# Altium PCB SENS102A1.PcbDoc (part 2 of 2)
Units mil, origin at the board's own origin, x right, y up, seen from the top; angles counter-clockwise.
Board outline 2760 x 2518.85 mil, 4 copper layers (Top Layer, Signal Layer 1, Signal Layer 2, Bottom Layer), stack 62.2 mil thick; 53 components, 21 nets, 101 pads, 383 vias.
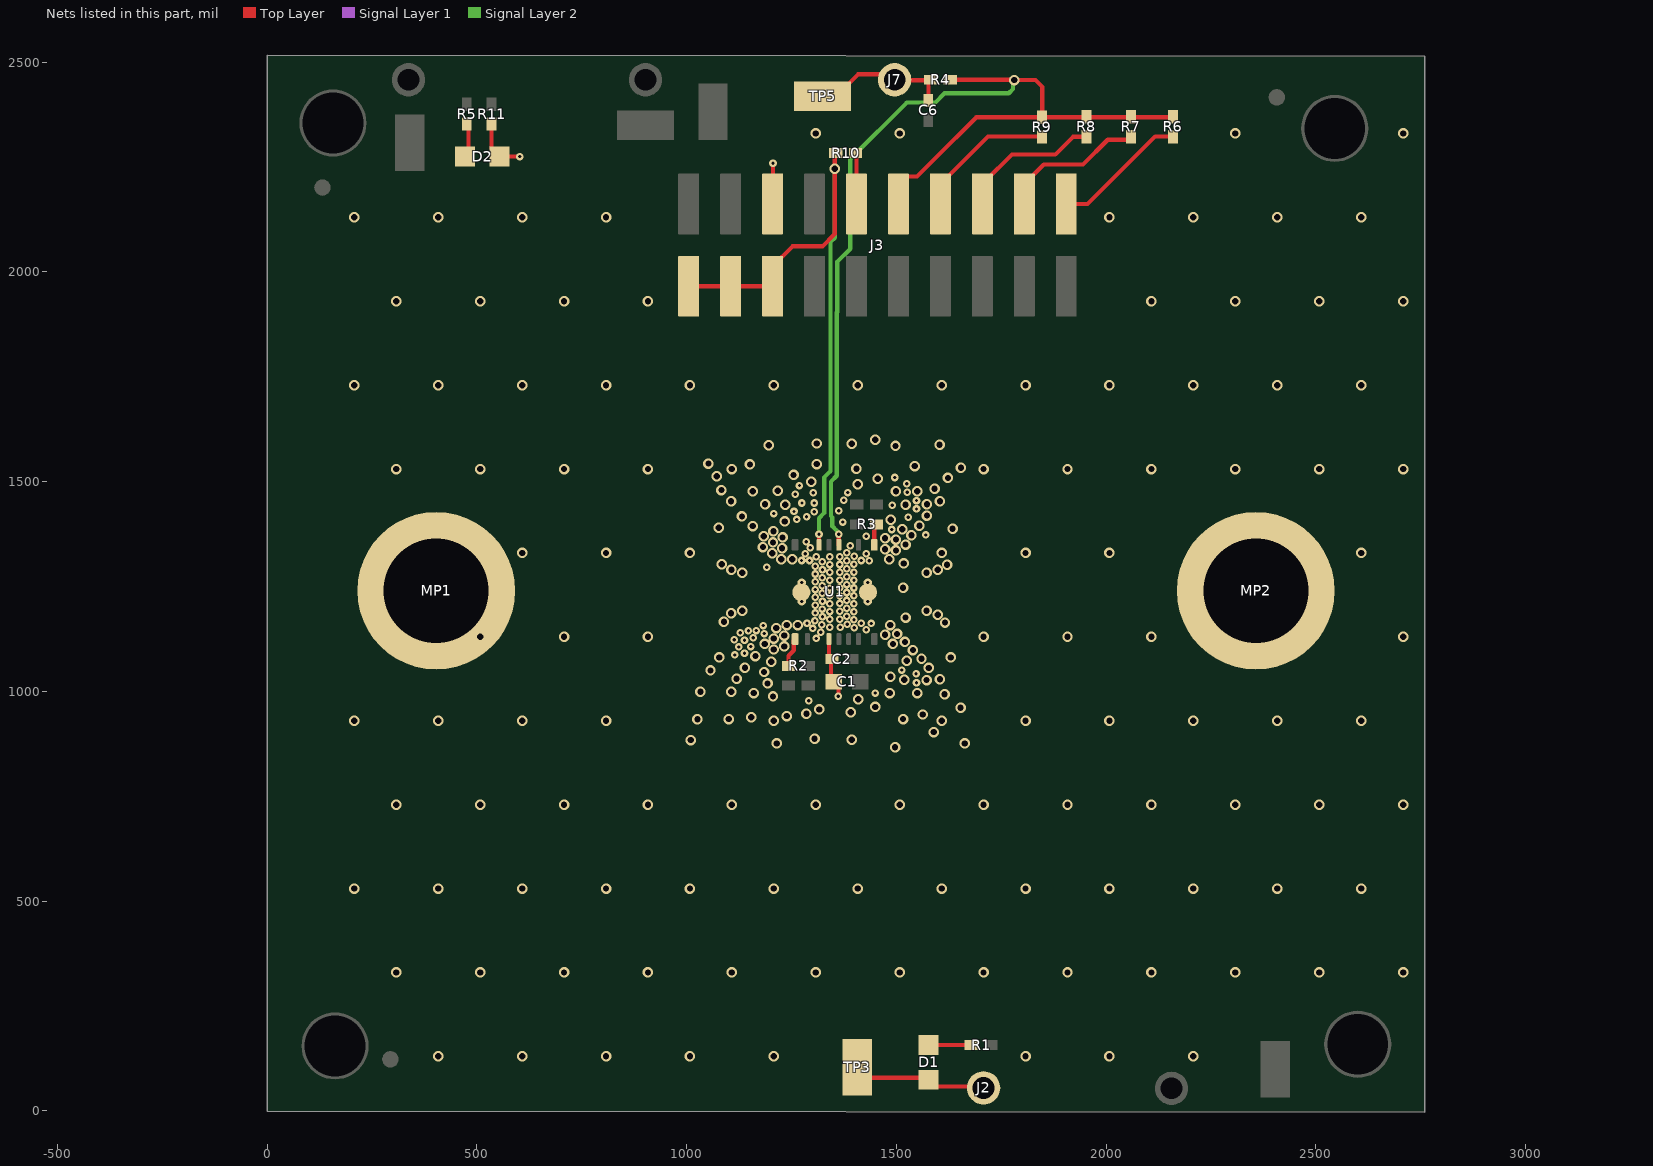
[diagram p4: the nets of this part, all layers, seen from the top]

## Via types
v1: diameter 25, hole 15, Top Layer to Bottom Layer, tented both sides, 247 vias
v2: diameter 18, hole 8, Top Layer to Bottom Layer, tented both sides, 132 vias
v3: diameter 19.68, hole 7.87, Top Layer to Bottom Layer, tented both sides, 4 vias

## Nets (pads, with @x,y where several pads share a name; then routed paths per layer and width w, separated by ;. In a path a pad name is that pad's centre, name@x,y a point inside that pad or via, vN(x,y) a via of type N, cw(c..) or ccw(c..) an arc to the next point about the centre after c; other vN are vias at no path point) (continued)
IS+: MP1.1 U1.15
  other v1: 408,130.12 608,130.12 808,130.12 1008,130.12 1208,130.12 308,330.12 508,330.12 708,330.12 908,330.12 1108,330.12 1308,330.12 208,530.12 408,530.12 608,530.12 808,530.12 1008,530.12 1208,530.12 308,730.12 508,730.12 708,730.12 908,730.12 1108,730.12 1308,730.12 1215,876 1010,884 1305,887 208,930.12 408,930.12 608,930.12 808,930.12 1208,930.12 1026,934 1100.59,934.04 1154.23,938.18 1239.09,941.28 1285.73,946.62 1316,957.12 1206,988 1160,996.12 1033,999.35 1106.48,999.35 1193,1019 1119.02,1030.18 1184.76,1046.32 1057,1050 1139.04,1056.66 1202,1071 1078,1081.12 1164.23,1084.43 1208.05,1099.96 1232.83,1107.2 1186,1113.12 1208,1126.12 508,1130.12 708,1130.12 908,1130.12 1232.92,1133.12 1214,1151.12 1238.83,1158.12 1265,1158.12 1089,1166.12 1106,1186.12 1133,1192.12 1133,1283.12 1107,1290.12 1084,1303.12 1226,1315.12 1252,1315.12 1204,1329.12 608,1330.12 808,1330.12 1008,1330.12 1227.59,1341.12 1182,1344.12 1206,1355.12 1228.79,1367.12 1184,1370.12 1207,1382.12 1077,1390.12 1158,1394.12 1234,1405.12 1132,1417.12 1235,1445.12 1187,1446.12 1106,1453.12 1158,1477.12 1217,1478.12 1083,1480 1297,1500.12 1072,1513.12 1255,1516.12 308,1530.12 508,1530.12 708,1530.12 908,1530.12 1108,1530.12 1151,1541.12 1310,1542 1052,1543.12 1196,1587.12 1310,1591 208,1730.12 408,1730.12 608,1730.12 808,1730.12 1008,1730.12 1208,1730.12 308,1930.12 508,1930.12 708,1930.12 908,1930.12 208,2130.12 408,2130.12 608,2130.12 808,2130.12 1308,2330.12
  other v2: 1291,978 1115,1087 1138,1091 1124,1106 1153,1107 1138,1122 1114,1123 1308.74,1126.25 1159,1128.12 1185,1138 1128.15,1139.85 1319.5,1141.12 1147.46,1145.06 1166,1145.12 1301,1150.12 1341,1153.12 1183,1157 1322,1159.12 1287,1162.12 1306,1168.12 1341,1171.79 1324,1178.07 1307,1187.12 1341,1190.46 1323,1196.34 1307,1205.69 1341,1209.12 1324,1215.28 1307,1224.27 1341,1227.79 1323,1233.67 1307,1242.84 1341,1246.46 1323,1252.12 1307,1261.41 1341,1265.12 1323,1271 1307,1279.98 1341,1283.79 1324,1290.23 1191,1296 1307,1298.55 1341,1302.46 1323,1309.12 1274,1312.12 1293,1312.12 1309,1321.12 1341,1321.12 1283,1328.12 1295,1342.12 1285,1357.2 1263,1410 1286,1416.12 1208,1424 1304,1428.12 1256,1429 1275,1449.12 1304,1449.12 1259,1470.12 1302.31,1474 1269,1490.74
  other v3: 1274.26,1214.49 1274.26,1259.76
IS-: MP2.1 U1.8
  other v1: 1808,130.12 2008,130.12 2208,130.12 1508,330.12 1708,330.12 1908,330.12 2108,330.12 2308,330.12 2508,330.12 2708,330.12 1408,530.12 1608,530.12 1808,530.12 2008,530.12 2208,530.12 2408,530.12 2608,530.12 1508,730.12 1708,730.12 1908,730.12 2108,730.12 2308,730.12 2508,730.12 2708,730.12 1497,867.12 1663,876 1394,885 1589,903.12 1608,930.12 1808,930.12 2008,930.12 2208,930.12 2408,930.12 2608,930.12 1516,934.12 1563,945 1391.04,950.19 1653,961 1450,963.12 1409,981.51 1615,993 1484,996.12 1550,996.12 1572,1027.12 1519,1028.12 1604,1029 1486,1035 1577.48,1056 1525,1073.12 1559.98,1077.64 1630,1081.12 1539.62,1098.62 1492,1113.09 1520.48,1118 1708,1130.12 1908,1130.12 2108,1130.12 2708,1130.12 1473.08,1135.12 1501.68,1137.15 1485.68,1158.15 1616,1164.12 1522,1176.11 1599,1183.12 1572,1192.12 1516,1247.12 1572,1283.12 1599,1290.12 1621,1302.12 1518,1305 1483,1315.12 1608,1330.12 1808,1330.12 2008,1330.12 2608,1330.12 1499,1336.12 1473,1339.12 1522,1350.12 1499,1362.12 1473.08,1365.12 1536,1372.12 1513.81,1386.85 1634,1388.12 1555,1395.12 1486.84,1409.57 1573,1419.12 1522,1445.12 1573,1446.12 1604,1453.12 1499,1477.12 1550,1477.12 1591,1483 1408,1494.12 1456,1507.12 1623,1509 1708,1530.12 1908,1530.12 2108,1530.12 2308,1530.12 2508,1530.12 2708,1530.12 1405,1531.12 1654,1533.12 1544,1537.12 1498,1585.12 1603,1588 1393.7,1590.54 1450,1600 1408,1730.12 1608,1730.12 1808,1730.12 2008,1730.12 2208,1730.12 2408,1730.12 2608,1730.12 2108,1930.12 2308,1930.12 2508,1930.12 2708,1930.12 2008,2130.12 2208,2130.12 2408,2130.12 2608,2130.12 1508,2330.12 2308,2330.12 2708,2330.12
  other v2: 1450,996.12 1548,1021 1547,1042 1513,1051 1427.98,1146.83 1400,1152.12 1366,1153.12 1383,1160.12 1416,1162.12 1439.85,1162 1399,1171.12 1365,1171.79 1382,1179.04 1399,1189.98 1365,1191.12 1382,1197.96 1399,1208.84 1365,1209.69 1382,1216.89 1365,1228.27 1399,1227.69 1382,1235.81 1399,1246.55 1365,1246.84 1382,1254.73 1365,1265.41 1399,1265.41 1382,1273.65 1365,1283.98 1399,1284.27 1382,1292.57 1365,1302.55 1399,1303.12 1382,1311.49 1416,1312.12 1435.67,1311.8 1365,1321.12 1399.58,1322.12 1427.98,1328.46 1382,1330.41 1390,1347.12 1428,1370.12 1570,1373 1489,1386 1372.62,1403.73 1528,1415 1363,1430.96 1548,1435 1490,1444 1548,1455 1375,1456 1384,1474.12 1526,1475 1525,1495 1496,1510
  other v3: 1431.74,1214.49 1431.74,1259.76
NetD1_2: D1.2 R1.2 | length 96.5
  Top Layer w10: D1.2@1577,157 R1.2@1673.5,157
NetD2_2: D2.2 R5.1 | length 70
  Top Layer w10: D2.2@471.66,2275 480,2283.34 R5.1@480,2341.5
NetJ3_10: J3.10 R10.2 | length 114.9
  Top Layer w10: J3.10@1398,2172 1405,2179 1405,2280.62 R10.2@1402.62,2283
NetJ3_14: J3.14 R9.2 | length 333
  Top Layer w10: J3.14@1605,2162 1605,2209.5 1718.5,2323 R9.2@1843,2323 ; R9.2@1846,2327 R9.2@1846.36,2326.64
NetJ3_16: J3.16 R8.1 | length 286.9
  Top Layer w10: J3.16@1707,2216 1711.5,2216 1775.5,2280 1879,2280 1921,2322 R8.1@1950,2322
NetJ3_18: J3.18 R7.2 | length 348.6
  Top Layer w10: J3.18@1805,2162 1805,2209.5 1851.5,2256 1945,2256 2004,2315 2052.19,2315 2059,2321.81 R7.2@2059,2322.38
NetJ3_20: J3.20 R6.2 | length 321.7
  Top Layer w10: J3.20@1905,2162 1956,2162 2117,2323 R6.2@2160,2323
OUT: J3.12 R4.1 R6.1 R7.1 R8.2 R9.1 U1.11 | length 2494
  Top Layer w10: U1.11@1362.84,1349.33 1362.92,1349.41 1362.92,1374.92 v2(1363,1375) ; J3.12@1505,2162 1505,2207.5 1525,2227.5 1549.5,2227.5 1590,2268 1690.62,2368.62 R9.1@1847,2368.62 ; R4.1@1628.62,2458 v1@1780,2458 ; v1(1781,2457.38) 1831.62,2457.38 1848,2441 R9.1@1848,2372 ; R9.1@1850,2368.62 1953,2368.62 2059,2368.62 2163.62,2368.62 R6.1@2164,2369
  Signal Layer 2 w10: v2@1361.47,1376.53 v2(1363,1375) 1363,1377.16 1358.22,1381.94 1358.22,1382.87 1347.19,1393.9 1347.19,1414.77 1344,1417.96 1344,1500 1358,1514 1358,1903 1359,1904 1359,2024 1390,2055 1390,2269 1525,2404 1593,2404 1615,2426 1768,2426 1778.13,2436.13 1778.13,2453.13 v1@1784,2459
OUT_FLT: C6.2 J7.1 R4.2 TP5.1 | length 336.5
  Top Layer w10: TP5.1@1324,2419 1356.5,2419 1408.5,2471 1489,2471 J7.1@1503,2457 ; J7.1@1497,2457 J7.1@1503,2457 ; J7.1@1504,2456 J7.1@1503,2457 ; C6.2@1576,2408.62 1577,2409.62 1577,2457 J7.1@1503,2457
REF: J3.1 J3.3 J3.5 R10.1 U1.13 | length 1522.8
  Top Layer w10: J3.1@1005,1966 J3.3@1105,1966 1197,1966 J3.5@1199,1964 ; J3.5@1205,1974 1205,2013.5 1252.5,2061 1324,2061 1353.28,2090.28 v1(1353.28,2246.1) R10.1@1353.28,2282 ; U1.13@1315.6,1349.33 v2(1315.6,1375)
  Signal Layer 1 w10: v2@1315.6,1377.16 v2(1315.6,1375) v2@1317.13,1376.53
  Signal Layer 2 w10: v2(1315.6,1375) 1315.6,1412.85 1328,1425.25 1328,1510 1343,1525 1343,2071 1353.28,2081.28 v1(1353.28,2246.1)
SH+: R2.1 U1.1 | length 70.8
  Top Layer w10: R2.1@1242.62,1060.71 1242.62,1085.18 1255.64,1098.19 1255.64,1122.04 U1.1@1258.51,1124.92
SH-: R3.1 U1.9 | length 51
  Top Layer w10: U1.9@1447.49,1349.33 1447.49,1392.5 R3.1@1452.99,1398
VS: C1.1 C2.1 D1.1 D2.1 J2.1 J3.6 R11.1 TP3.1 U1.3 | length 644.4
  Top Layer w10: R11.1@535,2341.5 535,2294.34 D2.1@554.34,2275 v2(602.49,2275) ; J3.6@1205,2188 1206,2189 v2(1206,2259) ; U1.3@1339.17,1124.86 U1.3@1339.22,1124.92 1339.22,1080.87 1344.5,1075.58 C1.1@1344.5,1031 ; C1.1@1357.5,1021.19 1361.89,1016.8 v2(1361.89,988.19) ; TP3.1@1407,104 1432,79 D1.1@1577,79 ; D1.1@1577,74.32 1593.32,58 1705,58 J2.1@1708,55
pads on no net: FID1.1 FID2.1 FID3.1 H1.0 H2.0 H3.0 H4.0 J3.7 J3.8 LBL1.0 SH-J1.0 SH-J2.0 SH-J3.0

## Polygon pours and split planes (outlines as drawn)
IS+ on Bottom Layer "BOTTOM_LAYER_IS+_P032" (solid, remove dead copper, pour order 32): 0,0 1350,0 1350,2517 0,2517
IS- on Bottom Layer "BOTTOM_LAYER_IS-_P034" (solid, remove dead copper, pour order 34): 1350,0 2760,0 2760,2517 1350,2517
IS- on Top Layer "TOP_LAYER_IS-_P028" (solid, pour order 28): 1350,0 2760,0 2760,2517 1350,2517
IS+ on Top Layer "TOP_LAYER_IS+_P026" (solid, remove dead copper, pour order 26): 1.72,5 1351.72,5 1351.72,2522 1.72,2522
GND on Signal Layer 2 "SIGNAL_LAYER_2_GND_P054" (solid, remove dead copper, pour order 54): 0,0 2760,0 2760,2518 0,2517
GND on Signal Layer 2 "SIGNAL_LAYER_2_GND_P049" (solid, remove dead copper, pour order 49): 2765,-1 2758,6 2758,2514 0,2514 -14,2500 -19,2500 2,2521 12,2511 2760,2511 2760,4 2758,2 2758,-1
VS on Signal Layer 1 "SIGNAL_LAYER_1_VS_P053" (solid, remove dead copper, pour order 53): 0,0 2760,0 2760,2517 0,2517

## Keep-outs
Keep-Out Layer:
  text ".Layer_Name" at 277,-994.37 h60

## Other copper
Top Layer:
  text ".Layer_Name" at 277,-994.37 h60
Bottom Layer:
  text ".Layer_Name" at 277,-994.37 h60

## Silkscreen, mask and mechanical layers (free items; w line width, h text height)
Top Overlay:
  lines w10: 983,1647 1224,1647 ; 1382,1647 1940,1647
  text "OUT" at 1156,2437 h30
  text "Ext" at 825,2249 h30
  text "ALERT" at 330,2155 h30
  text "10 5X" at 1887,1884 h40 r270
  text "9 4X" at 1788,1850 h40 r270
  text "2 GND" at 1086,1849 h40 r270
  text "3 VS" at 1186,1849 h40 r270
  text "6" at 1489,1849 h40 r270
  text "7 2X" at 1586,1849 h40 r270
  text "8 3X" at 1688,1849 h40 r270
  text "4 NC" at 1286,1848 h40 r270
  text "5*" at 1385,1848 h40 r270
  text "1 Ext" at 985,1844 h40 r270
  text "1X" at 1490,1842 h40 r270
  text "REF" at 1050,1590 h40
  text "Gain (*Remove for 1X)" at 1376,1590 h40
  text "IS-" at 1926,1251 h40
  text "IS+" at 719,1250 h40
  text "DANGER HIGH VOLTAGE" at -282,604 h80
  text "CAUTION HOT SURFACE" at 1367,426 h80
  text "'.PRJ_Title' / .PRJ_Number.SCH_REV" at 63,425.62 h40
  text ".Layer_Name" at 277,-994.37 h60
Bottom Overlay:
  text ".Layer_Name" at 277,-994.37 h60
Top Paste:
  text ".Layer_Name" at 277,-994.37 h60
Bottom Paste:
  text ".Layer_Name" at 277,-994.37 h60
Top Solder:
  text ".Layer_Name" at 277,-994.37 h60
  text ".Layer_Name" at 277,-994.37 h60
Bottom Solder:
  text ".Layer_Name" at 277,-994.37 h60
Drill Guide:
  text ".Layer_Name" at 277,-994.37 h60
M1 Board Outline:
  the board outline again, w10
  text ".Layer_Name" at 277,-994.37 h60
M2 Board Dimensions:
  rectangle: -353,-547.88 -228,-422.88
  rectangle: -228,-671.88 147,-546.88
  text ".Layer_Name" at 277,-994.37 h60
M3 3D STEP Top:
  text ".Layer_Name" at 277,-994.37 h60
M4 3D STEP Bottom:
  text ".Layer_Name" at 277,-994.37 h60
M5 Assembly Top:
  text "COMPONENTS MARKED 'DNP' SHOULD NOT BE POPULATED." at 877,-370.88 h60
  text "ASSEMBLY VARIANT:" at 853,-569.88 h60
  text ".VariantName" at 1889,-569.88 h60
  text "PCB VIEWED FROM TOP SIDE" at -528.5,-791.54 h60
  text "BOARD #:" at 1948,-791.54 h60
  text ".PRJ_Number" at 2493.5,-791.54 h60
  text "REV:" at 3338,-791.54 h60
  text ".PCB_Rev" at 3629.5,-791.54 h60
  text "SVN REV:" at 4176,-791.54 h60
  text ".VersionControl_RevNumber" at 4682,-791.54 h60
  text "TID #:" at 1948,-994.88 h60
  text ".TID" at 2493.5,-994.88 h60
  text "PLOT NAME =" at -528.5,-1200.21 h60
  text ".plot_File_Name" at 277,-1200.21 h60
  text "GENERATED    :" at 1950,-1200.21 h60
  text ".Print_Date" at 2819.5,-1200.21 h60
  text ".Print_Time" at 3548.5,-1200.21 h60
  text "TEXAS INSTRUMENTS" at 4813,-1200.21 h60
M6 Assembly Bottom:
  text "COMPONENTS MARKED 'DNP' SHOULD NOT BE POPULATED." at 5773,24.12 h60
  text ".VariantName" at 4758,-569.88 h60
  text "ASSEMBLY VARIANT:" at 5797,-569.88 h60
  text ".VersionControl_RevNumber" at 735.5,-792.04 h60
  text "SVN REV:" at 1241.5,-792.04 h60
  text ".PCB_Rev" at 1788,-792.04 h60
  text "REV:" at 2079.5,-792.04 h60
  text ".PRJ_Number" at 2924,-792.04 h60
  text "BOARD #:" at 3469.5,-792.04 h60
  text "PCB VIEWED FROM BOTTOM SIDE" at 5946,-792.04 h60
  text ".TID" at 2924,-995.38 h60
  text "TID #:" at 3469.5,-995.38 h60
  text "TEXAS INSTRUMENTS" at 604.5,-1200.71 h60
  text ".Print_Time" at 1869,-1200.71 h60
  text ".Print_Date" at 2598,-1200.71 h60
  text "GENERATED    :" at 3467.5,-1200.71 h60
  text ".plot_File_Name" at 5140.5,-1200.71 h60
  text "PLOT NAME =" at 5946,-1200.71 h60
M9 Title Sheet:
  drawing of 18 lines, arcs and shapes, not listed
  text "1" at 439.84,7900.62 h70
  text "2" at 2935.5,7900.62 h70
  text "3" at 5424.84,7900.62 h70
  text "4" at 7931.51,7900.62 h70
  text "5" at 10430.5,7900.62 h70
  text "6" at 12935.5,7900.62 h70
  text "A" at -716.5,6757.62 h70
  text "A" at 14083.5,6757.62 h70
  text "B" at -716.5,4377.62 h70
  text "B" at 14083.5,4377.62 h70
  text "C" at -716.5,2002.62 h70
  text "C" at 14083.5,2002.62 h70
  text "PROJECT TITLE:" at 11043.5,141.62 h45
  text ".PRJ_Title" at 11093.5,8.3 h70
  text "DESIGNED FOR:" at 11043.5,-159.38 h45
  text ".PRJ_Customer" at 11093.5,-299.38 h70
  text "D" at -716.5,-367.38 h70
  text "D" at 14083.5,-367.38 h70
  text "FILE NAME:" at 11043.5,-459.38 h45
  text ".PCB_File_Name_No_Path" at 11093.5,-579.38 h70
  text "Texas Instruments (TI) and/or its licensors do not warrant the accuracy or completeness of this specification" at 6074,-741.22 h45
  text "ENGINEER:" at 11043.5,-749.38 h45
  text "LAYOUT BY:" at 12548.5,-749.38 h45
  text "or any information contained therein. TI and/or its licensors do not warrant that this design will meet" at 6029.01,-853.88 h45
  text ".PRJ_Engineer" at 11093.5,-904.37 h70
  text ".PCB_Layout" at 12599,-904.37 h70
  text "the specifications, will be suitable for your application or fit for any particular purpose, or will operate in" at 6029.01,-966.55 h45
  text ".Layer_Name" at 277,-994.37 h60
  text "ALTIUM DESIGNER VERSION:" at 12548.5,-1059.38 h45
  text "an implementation. TI and/or its licensors do not warrant that the design is production worthy. You should" at 6029.01,-1079.21 h45
  text "completely validate and test your design implementation to confirm the system functionality for your application." at 6074,-1191.88 h45
  text ".print_Scale" at 11093.5,-1192.7 h70
  text ".Application_BuildNumber" at 12599,-1192.7 h70
  text "1" at 439.84,-1399.38 h70
  text "2" at 2935.5,-1399.38 h70
  text "3" at 5424.84,-1399.38 h70
  text "4" at 7931.51,-1399.38 h70
  text "5" at 10430.5,-1399.38 h70
  text "6" at 12935.5,-1399.38 h70
M10 Fab Notes:
  text "DESIGN INFORMATION" at 12082.02,6220.3 h60
  text "MIN. TRACK WIDTH:" at 11437.46,6088.17 h60
  text "8" at 12533.7,6088.17 h60
  text "MIL" at 12688.46,6088.17 h60
  text "mm" at 12812,5968.12 h60
  text "MIN. CLEARANCE:" at 11437.46,5964.04 h60
  text "0.127" at 12473.7,5964.05 h60
  text "MIN. VIA PAD SIZE:" at 11437.46,5839.92 h60
  text "18" at 12503.71,5839.92 h60
  text "MIL" at 12688.46,5839.92 h60
  text "5 MIL" at 12132.46,5710.02 h60
  text "MINIMUM ANNULAR RING" at 11108.23,5701.8 h60
  text "EXTERNAL" at 12840.46,5701.8 h60
  text "PER" at 11308.23,5591.67 h60
  text "IPC-D-275 CLASS 2 LEVEL C" at 11528.23,5591.67 h60
  text "MIL, HOLES" at 13016.46,5491.19 h60
  text "+/-" at 12624,5482.61 h60
  text "+/-" at 13478,5482.61 h60
  text "REGISTRATION TOLERANCES:" at 11108.23,5481.54 h60
  text "METAL" at 12308,5481.54 h60
  text "5" at 12884.2,5481.54 h60
  text "3" at 13717.2,5481.54 h60
  text "MIL" at 13833.46,5481.54 h60
  text "HOLE SIZE TOLERANCE (UNLESS OTHERWISE SPECIFIED):" at 11108.23,5383.23 h60
  text "+/-" at 13478,5380.35 h60
  text "3" at 13717.2,5379.29 h60
  text "MIL" at 13833.46,5379.29 h60
  text "MATERIAL:" at 11033.46,5241.64 h60
  text "FR-4 High Tg" at 12019.9,5113.12 h60
  text "X" at 11875.46,5105.13 h60
  text "FR-408" at 11454.46,5100.61 h60
  text "OTHER" at 12942.46,5100.61 h60
  text "63 MIL (1.6mm) +/-10%" at 11774.56,4957.58 h60
  text "X" at 11654.46,4955.13 h60
  text "THICKNESS:" at 11108.23,4949.36 h60
  text "OTHER" at 13059.46,4949.36 h60
  text "TOLERANCE:" at 11108.23,4811.05 h60
  text "X" at 11956.46,4811.05 h60
  text "ANSI IPC-6012 TYPE 3 CLASS 2" at 12134.48,4811.05 h60
  text "OTHER +/-" at 12134.46,4666.86 h60
  text "BOW & TWIST:" at 11108.23,4521.67 h60
  text "X" at 11956.46,4521.67 h60
  text "ANSI IPC-6012 TYPE 3 CLASS 2" at 12134.48,4521.67 h60
  text "OTHER +/-" at 12134.46,4374.97 h60
  text "DRILLING:" at 11033.46,4244.35 h60
  text "NC_DRILL FILES" at 12794.46,4139.16 h60
  text "REFERENCE:" at 11108.23,4135.23 h60
  text "X" at 11765.46,4135.13 h60
  text "AS SHOWN" at 11943.46,4135.23 h60
  text "X" at 12666.46,4135.23 h60
  text "OTHER" at 13092.46,3992.97 h60
  text "PTH COPPER THICKNESS:" at 11107.91,3989.45 h60
  text "X" at 12247.14,3989.45 h60
  text "20-30 um" at 12375.14,3989.45 h60
  text "BOARD FINISH:" at 11033.46,3841.85 h60
  text "SILKSCREEN:" at 11188.68,3731.72 h60
  text "X" at 12146.46,3731.72 h60
  text "TOP" at 12263.46,3731.72 h60
  text "X" at 12656.46,3731.72 h60
  text "BOTTOM" at 12774.46,3731.72 h60
  text "SILKSCREEN COLOR:" at 11188.68,3576.53 h60
  text "X" at 12145.46,3576.53 h60
  text "WHITE" at 12263.46,3576.53 h60
  text "OTHER" at 12774.46,3576.53 h60
  text "X" at 12276.46,3433.09 h60
  text "GREEN" at 12394.46,3433.09 h60
  text "OTHER" at 13012.46,3433.09 h60
  text "SOLDER RESIST COLOR:" at 11188.68,3426.22 h60
  text "X" at 12276.46,3278.83 h60
  text "MATTE" at 12394.46,3278.83 h60
  text "SEMI-GLOSS" at 13012,3278.2 h60
  text "IMMERSION GOLD (ENIG)" at 12094.46,3106.06 h60
  text "ENEPIG" at 13432,3098.84 h60
  text "SURFACE FINISH:" at 11033.46,3097.84 h60
  text "X" at 11916.46,3097.84 h60
  text "IMM. TIN/SILVER OR EQUIV" at 11363,2960.53 h60
  text "OTHER" at 12794.46,2956.59 h60
  text "ARRAY/PANEL:" at 11033.46,2801.21 h60
  text "CUT AND TRIM PER M1 BOARD OUTLINE" at 12094.46,2792.99 h60
  text "N.C. ROUTE" at 12094.46,2657.02 h60
  text "X" at 12782.46,2657.02 h60
  text "V. SCORE" at 12960.46,2657.02 h60
  text "CERTIFICATION:" at 11033.46,2527.9 h60
  text "MATERIALS AND WORKMANSHIP FOR ALL PCBS" at 11758.46,2527.9 h60
  text "TO MEET OR EXCEED THE REQUIREMENTS OF:" at 11758.46,2433.83 h60
  text "X" at 11395.97,2305.2 h60
  text "ANSI IPC-A-600F CLASS ->" at 11523.96,2305.2 h60
  text "X" at 13171.97,2305.2 h60
  text "2" at 13281.96,2305.2 h60
  text "1" at 12966.96,2303.71 h60
  text "3" at 13635.96,2303.71 h60
  text "X" at 12207.97,2157.52 h60
  text "RoHS" at 12335.96,2157.52 h60
  text "OTHER" at 12980.36,2157.52 h60
  text "PER ORDER" at 13377.42,2157.52 h60
  text "ALL BOARDS MUST MEET OR EXCEED UL94-V0 REQUIREMENTS." at 11061,2003.69 h60
  text "PCB MUST BEAR THE UL94V-0 UL REGISTERED MATERIAL ID NUMBER" at 11061,1887.63 h60
  text "ADDITIONAL REQUIREMENTS:" at 11033.46,1718.2 h60
  text "MICROSECTION:" at 11108.23,1611.08 h60
  text "NO" at 12013.96,1611.08 h60
  text "X" at 12321,1479.12 h60
  text "REQUIRED" at 12875.46,1466.74 h60
  text "BARE BOARD ELEC. TEST:" at 11108.23,1463.89 h60
  text "NONE" at 12413.96,1463.89 h60
  text "PER ORDER" at 13467.46,1463.89 h60
  text "No VIAS REQUIRE NON-CONDUCTIVE FILL AND PLANARIZE" at 11276.38,1258.94 h59
  text "No VIAS REQUIRE CONDUCTIVE FILL AND PLANARIZE" at 11284.38,1154.97 h60
  text "OUTER XX MIL TRACES REQUIRE 50 OHM SINGLE-ENDED IMPEDANCE" at 11283.39,991.58 h58
  text "LAYER 2 & 3 (INNER LAYERS) 17 MIL WIDE, XX MIL SPACE / TRACES REQUIRE 100 OHM DIFFERENTIAL IMPEDANCE" at 11237,649.12 h60 r0.3
  text ".Layer_Name" at 277,-994.37 h60
M11 Gerber Information:
  text "ALL ARTWORK VIEWED FROM TOP SIDE" at -528.5,-791.54 h60
  text "BOARD #:" at 1948,-791.54 h60
  text ".PRJ_Number" at 2493.5,-791.54 h60
  text "REV:" at 3338,-791.54 h60
  text ".PCB_Rev" at 3629.5,-791.54 h60
  text "SVN REV:" at 4176,-791.54 h60
  text ".VersionControl_RevNumber" at 4682,-791.54 h60
  text "LAYER NAME =" at -528.5,-994.37 h60
  text "TID #:" at 1948,-994.88 h60
  text ".TID" at 2493.5,-994.88 h60
  text "PLOT NAME =" at -528.5,-1200.21 h60
  text ".plot_File_Name" at 277,-1200.21 h60
  text "GENERATED    :" at 1950,-1200.21 h60
  text ".Print_Date" at 2819.5,-1200.21 h60
  text ".Print_Time" at 3548.5,-1200.21 h60
  text "TEXAS INSTRUMENTS" at 4813,-1200.21 h60
M12 Stackup:
  drawing of 444 lines, arcs and shapes, not listed
  text "Layer" at 6413.09,5230.71 h60
  text "Name" at 6823,5230.71 h60
  text "Material" at 7762.74,5230.71 h60
  text "Thickness" at 8622.51,5230.71 h60
  text "Constant" at 9272.34,5230.71 h60
  text "Board Layer Stack" at 9842.2,5230.71 h60
  text "Top Overlay" at 6823,5110.71 h60
  text "Top Solder" at 6823,4990.71 h60
  text "Solder Resist" at 7762.74,4990.71 h60
  text "0.40mil" at 8622.51,4990.71 h60
  text "3.5" at 9272.34,4990.71 h60
  text "1" at 6413.09,4870.71 h60
  text "Top Layer" at 6823,4870.71 h60
  text "2.80mil" at 8622.51,4870.71 h60
  text "Dielectric1" at 6823,4750.71 h60
  text "FR-4" at 7762.74,4750.71 h60
  text "17.00mil" at 8622.51,4750.71 h60
  text "4.2" at 9272.34,4750.71 h60
  text "2" at 6413.09,4630.71 h60
  text "Signal Layer 1" at 6823,4630.71 h60
  text "2.80mil" at 8622.51,4630.71 h60
  text "Dielectric 2" at 6823,4510.71 h60
  text "FR-4" at 7762.74,4510.71 h60
  text "17.00mil" at 8622.51,4510.71 h60
  text "4.2" at 9272.34,4510.71 h60
  text "3" at 6413.09,4390.71 h60
  text "Signal Layer 2" at 6823,4390.71 h60
  text "2.80mil" at 8622.51,4390.71 h60
  text "Dielectric 3" at 6823,4270.71 h60
  text "FR-4" at 7762.74,4270.71 h60
  text "17.00mil" at 8622.51,4270.71 h60
  text "4.2" at 9272.34,4270.71 h60
  text "4" at 6413.09,4150.71 h60
  text "Bottom Layer" at 6823,4150.71 h60
  text "2.80mil" at 8622.51,4150.71 h60
  text "Bottom Solder" at 6823,4030.71 h60
  text "Solder Resist" at 7762.74,4030.71 h60
  text "0.40mil" at 8622.51,4030.71 h60
  text "3.5" at 9272.34,4030.71 h60
  text "Bottom Overlay" at 6823,3910.71 h60
  text ".Layer_Name" at 277,-994.37 h60
M13 Component Bodies Top:
  text ".Layer_Name" at 277,-994.37 h60
M14 Component Bodies Bottom:
  text ".Layer_Name" at 277,-994.37 h60
M15 Courtyards Top:
  text ".Layer_Name" at 277,-994.37 h60
M16 Courtyards Bottom:
  text ".Layer_Name" at 277,-994.37 h60
Drill Drawing:
  lines w10: 3034.09,3251.55 3047.9,3251.55 3061.72,3237.74 3075.53,3251.55 3089.34,3251.55 3075.53,3265.37 3089.34,3279.18 3075.53,3279.18 3061.72,3292.99 3047.9,3279.18 3034.09,3279.18 3047.9,3265.37 3034.09,3251.55 ; 3034.09,3375.87 3047.9,3375.87 3047.9,3362.06 3075.53,3362.06 3075.53,3375.87 3089.34,3375.87 3089.34,3403.5 3075.53,3403.5 3075.53,3417.31 3047.9,3417.31 3047.9,3403.5 3034.09,3403.5 3034.09,3375.87 ; 3034.09,3486.38 3089.34,3486.38 3089.34,3541.63 3034.09,3541.63 3034.09,3486.38 ; 3034.09,3665.95 3089.34,3665.95 3061.72,3610.7 3034.09,3665.95 ; 3034.09,3735.02 3034.09,3748.83 3047.9,3762.65 3034.09,3776.46 3034.09,3790.27 3047.9,3790.27 3061.72,3776.46 3075.53,3790.27 3089.34,3790.27 3089.34,3776.46 3075.53,3762.65 3089.34,3748.83 3089.34,3735.02 3075.53,3735.02 3061.72,3748.83 3047.9,3735.02 3034.09,3735.02 ; 3034.09,3886.97 3061.72,3859.34 3089.34,3886.97 3061.72,3914.59 3034.09,3886.97
  lines w12: 2984,3200.44 6141.36,3200.44 ; 2984,3946.36 6141.36,3946.36 ; 3321.86,3076.12 3321.86,4070.68 ; 3623.5,3076.12 3623.5,4070.68 ; 4216.3,3076.12 4216.3,4070.68 ; 4475.44,3076.12 4475.44,4070.68 ; 4850.6,3076.12 4850.6,4070.68 ; 5574.93,3076.12 5574.93,4070.68 ; 2984,3076.12 6141.36,3076.12 6141.36,4070.68 2984,4070.68 2984,3076.12
  text "Symbol" at 3058.59,3983.66 h72
  text "Count" at 3359.16,3983.66 h72
  text "Hole Size" at 3660.8,3983.66 h72
  text "Plated" at 4253.6,3983.66 h72
  text "Hole Type" at 4512.74,3983.66 h72
  text "Drill Layer Pair" at 4887.89,3983.66 h72
  text "Hole Tolerance" at 5612.22,3983.66 h72
  text "4" at 3359.16,3859.34 h60
  text "7.87mil (0.200mm)" at 3660.8,3859.34 h60
  text "PTH" at 4253.6,3859.34 h60
  text "Round" at 4512.74,3859.34 h60
  text "Top Layer - Bottom Layer" at 4887.89,3859.34 h60
  text "132" at 3359.16,3735.02 h60
  text "8.00mil (0.203mm)" at 3660.8,3735.02 h60
  text "PTH" at 4253.6,3735.02 h60
  text "Round" at 4512.74,3735.02 h60
  text "Top Layer - Bottom Layer" at 4887.89,3735.02 h60
  text "247" at 3359.16,3610.7 h60
  text "15.00mil (0.381mm)" at 3660.8,3610.7 h60
  text "PTH" at 4253.6,3610.7 h60
  text "Round" at 4512.74,3610.7 h60
  text "Top Layer - Bottom Layer" at 4887.89,3610.7 h60
  text "5" at 3359.16,3486.38 h60
  text "51.97mil (1.320mm)" at 3660.8,3486.38 h60
  text "PTH" at 4253.6,3486.38 h60
  text "Round" at 4512.74,3486.38 h60
  text "Top Layer - Bottom Layer" at 4887.89,3486.38 h60
  text "4" at 3359.16,3362.06 h60
  text "145.00mil (3.683mm)" at 3660.8,3362.06 h60
  text "PTH" at 4253.6,3362.06 h60
  text "Round" at 4512.74,3362.06 h60
  text "Top Layer - Bottom Layer" at 4887.89,3362.06 h60
  text "2" at 3359.16,3237.74 h60
  text "250.00mil (6.350mm)" at 3660.8,3237.74 h60
  text "PTH" at 4253.6,3237.74 h60
  text "Round" at 4512.74,3237.74 h60
  text "Top Layer - Bottom Layer" at 4887.89,3237.74 h60
  text "394 Total" at 3359.16,3113.42 h60
  text ".Layer_Name" at 277,-994.37 h60
M17 Embedded Cavity:
  text ".Layer_Name" at 277,-994.37 h60
M18 Embedded Assembly:
  text ".Layer_Name" at 277,-994.37 h60
M19 Embedded Keepout:
  text ".Layer_Name" at 277,-994.37 h60

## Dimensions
-56,2516 to -1,-1 on M2 Board Dimensions
0,2531 to 2760,2528 on M2 Board Dimensions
